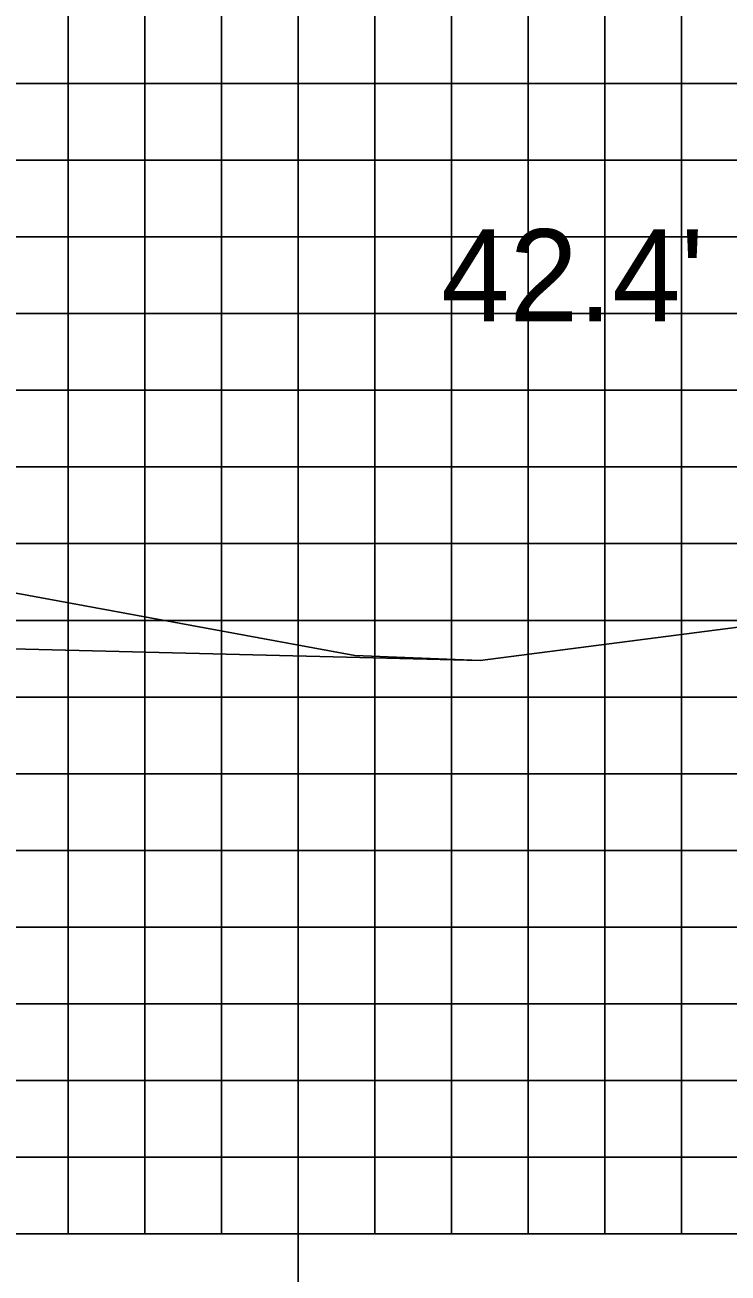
# Model space of a CAD drawing. Extents: x 844536 to 844879, y 363538 to 363758.
# Drawn here: x 844738.4 to 844747.57, y 363555.21 to 363571.48 of the extents above; entities that cross this region are included whole.
import ezdxf

# ---------------------------------------------------------------- set-up
doc = ezdxf.new("R2010")
doc.units = 0
for name, color, linetype in [('D_Roadway_SlopeLines', 7, 'Continuous'), ('D_Text_Standard', 7, 'Continuous'), ('MAJOR', 7, 'Continuous'), ('MINOR', 7, 'Continuous'), ('S_Roadway_Centerline', 7, 'Continuous')]:
    doc.layers.add(name, color=color, linetype=linetype)

msp = doc.modelspace()

# ---------------------------------------------------------------- linework, layer by layer
at = {"layer": 'D_Roadway_SlopeLines'}
msp.add_lwpolyline([(844738.235, 363563.349), (844744.336, 363563.196)], dxfattribs=at)
at = {"layer": 'MAJOR'}
for p, q in [((844741.964, 363555.721), (844741.964, 363580.721)), ((844561.964, 363570.721), (844841.964, 363570.721)), ((844561.964, 363565.721), (844841.964, 363565.721)), ((844561.964, 363560.721), (844841.964, 363560.721)), ((844561.964, 363555.721), (844841.964, 363555.721)), ((844561.964, 363555.721), (844841.964, 363555.721)), ((844741.964, 363553.717), (844741.964, 363555.721))]:
    msp.add_line(p, q, dxfattribs=at)
at = {"layer": 'MINOR'}
for p, q in [((844738.964, 363555.721), (844738.964, 363580.721)), ((844739.964, 363555.721), (844739.964, 363580.721)), ((844740.964, 363555.721), (844740.964, 363580.721)), ((844742.964, 363555.721), (844742.964, 363580.721)), ((844743.964, 363555.721), (844743.964, 363580.721)), ((844744.964, 363555.721), (844744.964, 363580.721)), ((844745.964, 363555.721), (844745.964, 363580.721)), ((844746.964, 363555.721), (844746.964, 363580.721)), ((844561.964, 363569.721), (844841.964, 363569.721)), ((844561.964, 363568.721), (844841.964, 363568.721)), ((844561.964, 363567.721), (844841.964, 363567.721)), ((844561.964, 363566.721), (844841.964, 363566.721)), ((844561.964, 363564.721), (844841.964, 363564.721)), ((844561.964, 363563.721), (844841.964, 363563.721)), ((844561.964, 363562.721), (844841.964, 363562.721)), ((844561.964, 363561.721), (844841.964, 363561.721)), ((844561.964, 363559.721), (844841.964, 363559.721)), ((844561.964, 363558.721), (844841.964, 363558.721)), ((844561.964, 363557.721), (844841.964, 363557.721)), ((844561.964, 363556.721), (844841.964, 363556.721))]:
    msp.add_line(p, q, dxfattribs=at)
at = {"layer": 'S_Roadway_Centerline'}
msp.add_lwpolyline([(844679.76, 363571.247), (844689.824, 363571.067), (844691.179, 363571.043), (844694.707, 363570.986), (844695.857, 363570.928), (844702.39, 363570.664), (844703.787, 363570.607), (844707.233, 363570.456), (844710.519, 363570.29), (844712.84, 363569.909), (844716.548, 363569.258), (844728.995, 363565.816), (844729.346, 363565.729), (844729.529, 363565.673), (844729.779, 363565.639), (844742.705, 363563.262), (844744.336, 363563.196), (844747.804, 363563.646)], dxfattribs=at)

# ---------------------------------------------------------------- texts
at = {"layer": 'D_Text_Standard'}
msp.add_text("42.4'", height=1.2, dxfattribs=at).set_placement((844743.829, 363567.621))

doc.saveas('drawing.dxf')
